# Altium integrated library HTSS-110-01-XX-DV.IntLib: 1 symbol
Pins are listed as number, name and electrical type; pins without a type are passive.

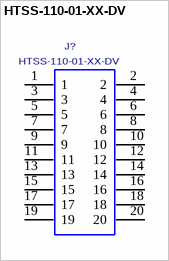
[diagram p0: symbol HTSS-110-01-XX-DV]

## HTSS-110-01-XX-DV
designator J?
HIGH TEMP TOP SHROUD; MANUFACTURER: SAMTEC
footprint HTSS-110-01-XX-DV
pins: 1, 2, 3, 4, 5, 6, 7, 8, 9, 10, 11, 12, 13, 14, 15, 16, 17, 18, 19, 20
